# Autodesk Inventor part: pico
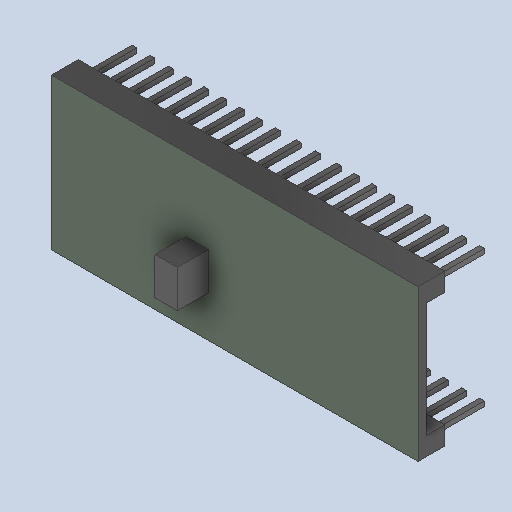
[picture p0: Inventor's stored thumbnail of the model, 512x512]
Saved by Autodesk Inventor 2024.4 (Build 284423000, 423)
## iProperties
Created: 2025-07
Part Number: pico
Material: Generic
Document SubType Name: Modeling
Designer: AdminForWorker
Density: 1 g/cm^3
Appearance: Default
Title: pico v1
Author: AdminForWorker
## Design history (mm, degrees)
feature "Body1"
body "Solid1"
